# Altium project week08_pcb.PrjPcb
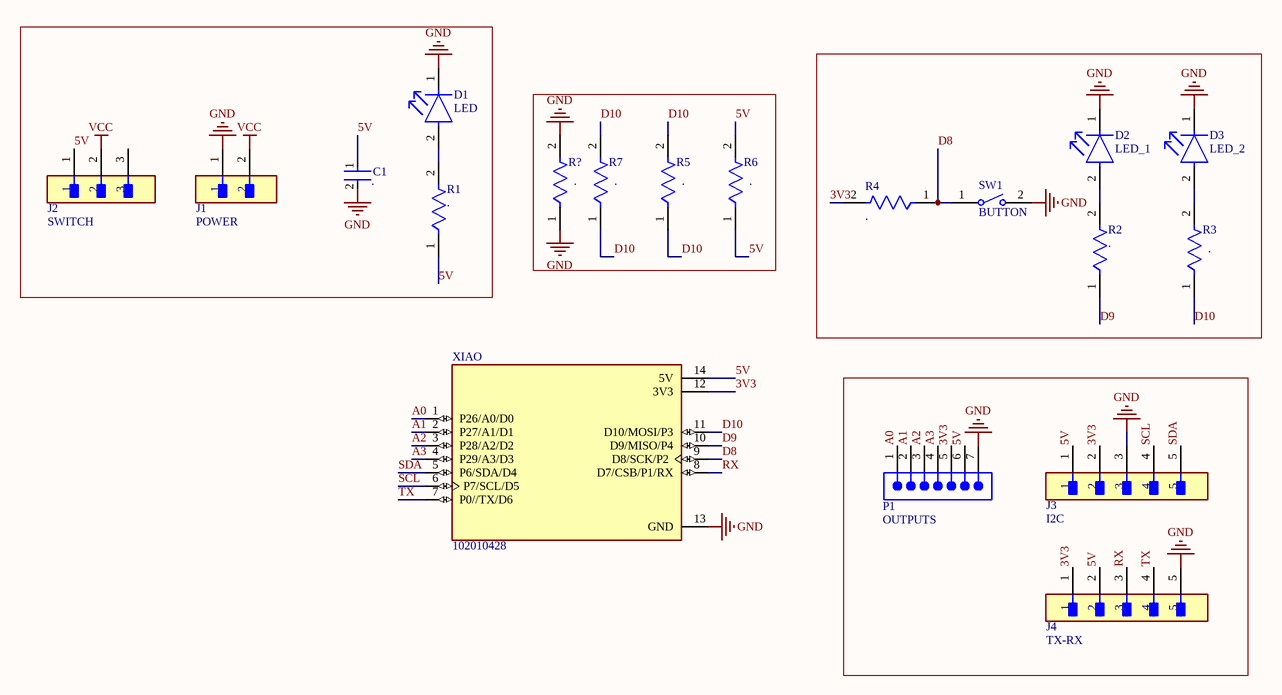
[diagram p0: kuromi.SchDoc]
1 sheet, 19 parts. Net scope: global (net labels, ports and power ports of the same name join across sheets).
Board file: kuromi.PcbDoc

## Sheet kuromi.SchDoc
size A4; SheetNumber: 1; SheetTotal: 1

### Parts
C1  .  [FP-C1206C-EB-MFG]
D1  LED  [FP-LTST-C150KSKT-MFG]
D2  LED_1  [FP-LTST-C150KSKT-MFG]
D3  LED_2  [FP-LTST-C150KSKT-MFG]
J1  POWER  [FP-TMM-102-01-L-S-MFG]
J2  SWITCH  [FP-PR20203VBNN-MFG]
J3  I2C  [FP-90120-0125-MFG]
J4  TX-RX  [FP-90120-0125-MFG]
P1  OUTPUTS  [SMTC-TSW-107-05-X-S]
R1  .  [FP-AC1206-MFG]
R2  .  [FP-AC1206-MFG]
R3  .  [FP-AC1206-MFG]
R4  .  [FP-AC1206-MFG]
R5  .  [FP-AC1206-MFG]
R6  .  [FP-AC1206-MFG]
R7  .  [FP-AC1206-MFG]
R?  .  [FP-AC1206-MFG]
SW1  BUTTON  [TECO-FSMSM-2_V]
XIAO  102010428  [MODULE_102010428]

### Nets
GND: C1.2 D1.1(C) D2.1(C) D3.1(C) J1.1 J3.3 J4.5 P1.7 R?.1 R?.2 SW1.2 XIAO.13(GND)
VCC: J1.2 J2.2
3V3: J3.2 J4.1 P1.5 R4.2 XIAO.12(3V3)
5V: C1.1 J2.1 J3.1 J4.2 P1.6 R1.1 R6.1 R6.2 XIAO.14(5V)
A0: P1.1 XIAO.1(P26/A0/D0)
A1: P1.2 XIAO.2(P27/A1/D1)
A2: P1.3 XIAO.3(P28/A2/D2)
A3: P1.4 XIAO.4(P29/A3/D3)
D8: R4.1 SW1.1 XIAO.9(D8/SCK/P2)
D9: R2.1 XIAO.10(D9/MISO/P4)
D10: R3.1 R5.1 R5.2 R7.1 R7.2 XIAO.11(D10/MOSI/P3)
RX: J4.3 XIAO.8(D7/CSB/P1/RX)
SCL: J3.4 XIAO.6(P7/SCL/D5)
SDA: J3.5 XIAO.5(P6/SDA/D4)
TX: J4.4 XIAO.7(P0//TX/D6)
NetD1_2: D1.2(A) R1.2
NetD2_2: D2.2(A) R2.2
NetD3_2: D3.2(A) R3.2

Not connected (* = marked no-connect by the designer): J2 3

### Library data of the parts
C1 = CMP-03020-023751-1: C1206 100 pF X8R 10.00% 50 V; Manufacturer: KEMET; Manufacturer Part Number: C1206C101K5HACTU; Capacitance: 100 pF; Temperature Coefficient: 15%; Voltage Rating: 50 V; Tolerance: 0.1; Automotive Grade: Grade 0; Value: 100 pF; Material: Ceramic
D1-D3 = CMP-2000-06618-2: LED YELLOW CLEAR 1206 SMD; Power Rating: 75mW; Wavelength: 588nm; Forward Current: 30mA; Test Current: 20mA; Viewing Angle: 130°; Forward Voltage: 2.4V; Luminous Intensity: 60mcd; Lens Style: Diffused; Number of Elements: 1; Reverse Voltage: 5V; Lens Color: Colorless; Dominant Wavelength: 587nm
J1 = CMP-02766-001606-1: CONN HEADER VERT 2POS 2MM; Number of Positions: 2; Gender: Male; Max Current Rating: 3.9A; Max Voltage Rating (AC): 500V
J2 = CMP-77940-000002-1: CONN HEADER VERT 3POS 2.54MM; Manufacturer Part Number: PR20203VBNN; Manufacturer: Metz Connect; Conn Orientation: Straight; Current Rating: 3A; Number Of Contacts: 3; Conn Gender: Male
J3 J4 = CMP-00257-00655425-1: 90120-0125 2.54mm Pitch C-Grid III Header, Single Row, Vertical, 5 Circuits, Tin (Sn) Plating; NexarPartId: 655425; Manufacturer Lifecycle Status: ACTIVE; Lead Length: 2.9mm; Number of Positions: 5; Current Rating: 3A; Mating Post Length: 6.75mm; Glow Wire Compliant: Non-compliant; Contact Resistance: 20mΩ; Voltage Rating: 350V; Gender: Male; Max Voltage Rating (DC): 350.35kV
P1 = CMP-1024-00402-1: 0.025" SQ Post Header, Through-hole, Vertical, -55 to 125 degC, 2.54 mm Pitch, 7-Pin, Male, RoHS; Manufacturer: Samtec; PartNumber: TSW-107-05-F-S; Pitch: 2.54 mm
R1-R7 R? = CMP-03412-032679-1: RES SMD 2.21K OHM 1% 1/4W 1206; Manufacturer: Yageo; Manufacturer Part Number: AC1206FR-072K21L; Automotive Grade: Grade 0; Voltage Rating: 200V; Tolerance: 0.01; Value: 2.21KΩ; Power Rating: 0.25W
SW1 = CMP-2000-07511-1: FSMSM Push Button Switch, 50 mA, -35 to 85 degC, 2-Pin SMD, RoHS, Bulk; Manufacturer: TE Connectivity; Actuator Length: 1.07mm; Electrical Life: 20000Cycles; Actuator Material: Polyamide; Current Rating: 50mA; Illumination Type: Illuminated; Voltage Rating (DC): 24V; Contact Resistance: 100mOhm; Case\/Package: SMD/SMT; Operating Force: 180gf; Switch Travel: 0.25mm; Max Voltage Rating (DC): 12V; Throw Configuration: SPST
XIAO = 102010428: RP2040 XIAO RP2040 series ARMÂ® CortexÂ®-M0+ MCU 32-Bit Embedded Evaluation Board; MF: Seeed Technology Co., Ltd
